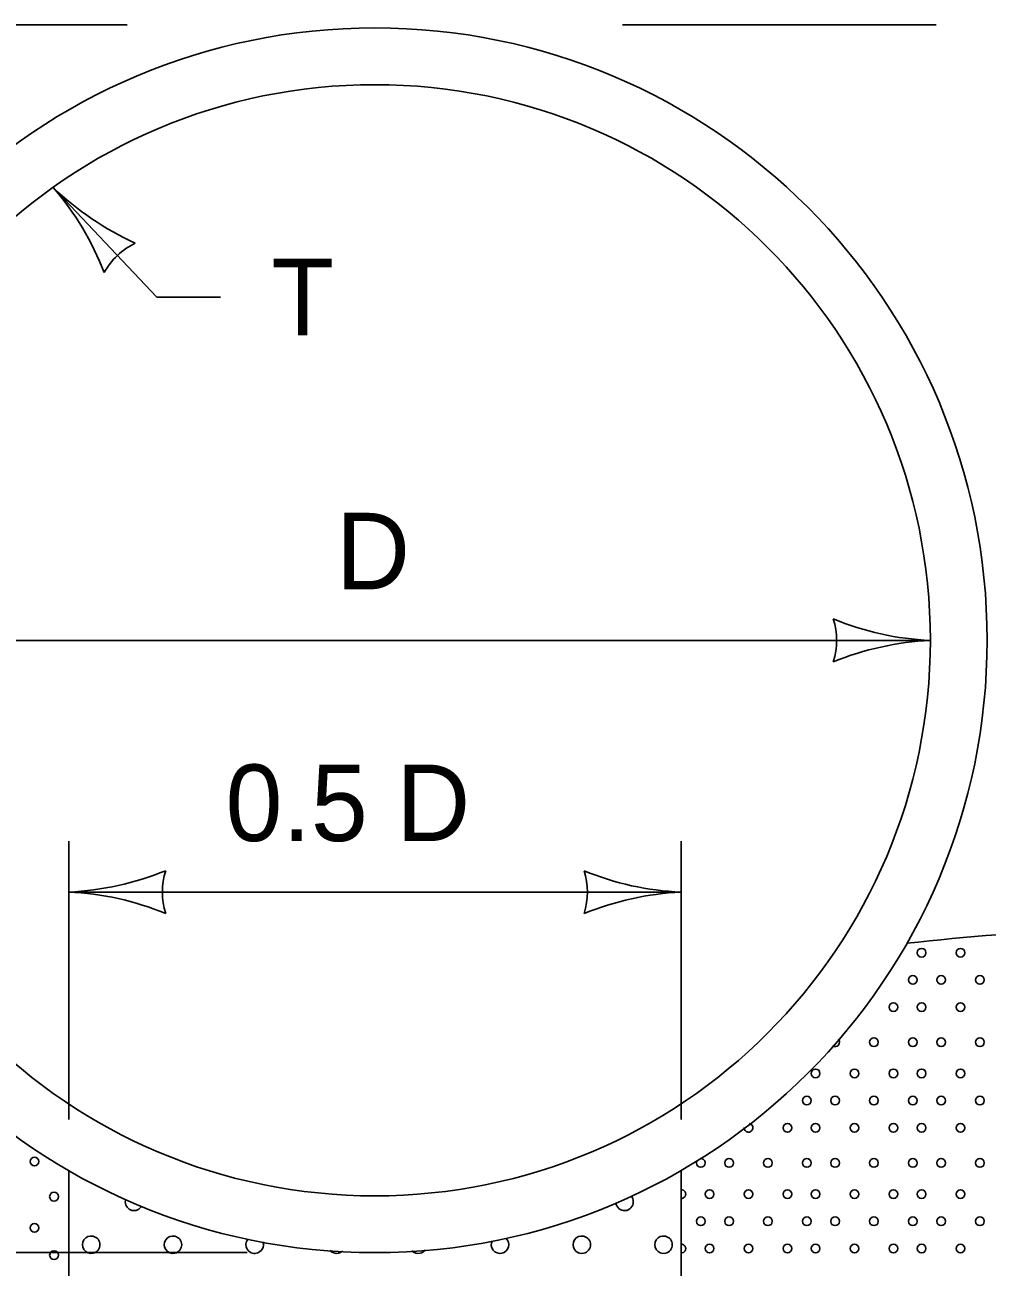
# Model space of a CAD drawing. Extents: x 49991.4 to 50021, y 49987.6 to 50011.4.
# Drawn here: x 50003.081 to 50003.835, y 49989.824 to 49990.797 of the extents above; entities that cross this region are included whole.
import ezdxf

# ---------------------------------------------------------------- set-up
doc = ezdxf.new("R2010")
doc.units = 0
for name, color, linetype in [('Level 1', 7, 'Continuous'), ('Level 2', 7, 'Continuous'), ('Level 3', 7, 'Continuous')]:
    doc.layers.add(name, color=color, linetype=linetype)

msp = doc.modelspace()

# ---------------------------------------------------------------- linework, layer by layer
at = {"layer": 'Level 1'}
for p, q in [((50001.91595, 49990.79724), (50003.16093, 49990.79724)), ((50003.54914, 49990.79724), (50003.79504, 49990.79724)), ((50003.11508, 49989.89915), (50003.11508, 49989.75269)), ((50003.59509, 49989.89921), (50003.59509, 49989.74091))]:
    msp.add_line(p, q, dxfattribs=at)
for centre, radius in [((50003.35503, 49990.31488), 0.47996), ((50003.35503, 49990.31488), 0.43545), ((50003.78366, 49990.07002), 0.00341), ((50003.81414, 49990.07002), 0.00341), ((50003.77676, 49990.04868), 0.00341), ((50003.7989, 49990.04868), 0.00341), ((50003.82938, 49990.04868), 0.00341), ((50003.82938, 49990.04868), 0.00341), ((50003.76152, 49990.02735), 0.00341), ((50003.78366, 49990.02735), 0.00341), ((50003.81414, 49990.02735), 0.00341), ((50003.70056, 49989.97542), 0.00341), ((50003.73104, 49989.97542), 0.00341), ((50003.76152, 49989.97542), 0.00341), ((50003.78366, 49989.97542), 0.00341), ((50003.81414, 49989.97542), 0.00341), ((50003.69366, 49989.95408), 0.00341), ((50003.7158, 49989.95408), 0.00341), ((50003.74628, 49989.95408), 0.00341), ((50003.74628, 49989.95408), 0.00341), ((50003.77676, 49989.95408), 0.00341), ((50003.7989, 49989.95408), 0.00341), ((50003.82938, 49989.95408), 0.00341), ((50003.82938, 49989.95408), 0.00341), ((50003.67841, 49989.93275), 0.00341), ((50003.70056, 49989.93275), 0.00341), ((50003.73104, 49989.93275), 0.00341), ((50003.76152, 49989.93275), 0.00341), ((50003.78366, 49989.93275), 0.00341), ((50003.81414, 49989.93275), 0.00341), ((50003.08831, 49989.9063), 0.00341), ((50003.61745, 49989.88082), 0.00341), ((50003.64793, 49989.88082), 0.00341), ((50003.67841, 49989.88082), 0.00341), ((50003.70056, 49989.88082), 0.00341), ((50003.73104, 49989.88082), 0.00341), ((50003.76152, 49989.88082), 0.00341), ((50003.78366, 49989.88082), 0.00341), ((50003.81414, 49989.88082), 0.00341), ((50003.61055, 49989.85948), 0.00341), ((50003.63269, 49989.85948), 0.00341), ((50003.66317, 49989.85948), 0.00341), ((50003.66317, 49989.85948), 0.00341), ((50003.69366, 49989.85948), 0.00341), ((50003.7158, 49989.85948), 0.00341), ((50003.74628, 49989.85948), 0.00341), ((50003.74628, 49989.85948), 0.00341), ((50003.77676, 49989.85948), 0.00341), ((50003.7989, 49989.85948), 0.00341), ((50003.82938, 49989.85948), 0.00341), ((50003.82938, 49989.85948), 0.00341), ((50003.08831, 49989.85437), 0.00341), ((50003.10355, 49989.83303), 0.00341), ((50003.10355, 49989.83303), 0.00341), ((50003.61745, 49989.83815), 0.00341), ((50003.64793, 49989.83815), 0.00341), ((50003.67841, 49989.83815), 0.00341), ((50003.70056, 49989.83815), 0.00341), ((50003.73104, 49989.83815), 0.00341), ((50003.76152, 49989.83815), 0.00341), ((50003.78366, 49989.83815), 0.00341), ((50003.81414, 49989.83815), 0.00341)]:
    msp.add_circle(centre, radius, dxfattribs=at)
for centre, radius, start, end in [((50003.7158, 49989.9998), 0.00341, 234.99733, 0), ((50003.7158, 49989.99992), 0.00341, 0, 44.24791), ((50003.74628, 49989.99992), 0.00341, 0, 180), ((50003.74628, 49989.9998), 0.00341, 180, 0), ((50003.74628, 49989.9998), 0.00341, 180, 0), ((50003.77676, 49989.99992), 0.00341, 0, 180), ((50003.77676, 49989.9998), 0.00341, 180, 0), ((50003.7989, 49989.99992), 0.00341, 0, 180), ((50003.7989, 49989.9998), 0.00341, 180, 0), ((50003.82938, 49989.99992), 0.00341, 0, 180), ((50003.82938, 49989.9998), 0.00341, 180, 0), ((50003.82938, 49989.9998), 0.00341, 180, 0), ((50003.64793, 49989.93275), 0.00341, 174.17681, 79.30151), ((50003.61055, 49989.90532), 0.00341, 150.81004, 180), ((50003.61055, 49989.9052), 0.00341, 180, 0), ((50003.61055, 49989.90532), 0.00341, 0, 92.56362), ((50003.63269, 49989.90532), 0.00341, 0, 180), ((50003.63269, 49989.9052), 0.00341, 180, 0), ((50003.66317, 49989.90532), 0.00341, 0, 180), ((50003.66317, 49989.9052), 0.00341, 180, 0), ((50003.66317, 49989.9052), 0.00341, 180, 0), ((50003.69366, 49989.90532), 0.00341, 0, 180), ((50003.69366, 49989.9052), 0.00341, 180, 0), ((50003.7158, 49989.90532), 0.00341, 0, 180), ((50003.7158, 49989.9052), 0.00341, 180, 0), ((50003.74628, 49989.90532), 0.00341, 0, 180), ((50003.74628, 49989.9052), 0.00341, 180, 0), ((50003.74628, 49989.9052), 0.00341, 180, 0), ((50003.77676, 49989.90532), 0.00341, 0, 180), ((50003.77676, 49989.9052), 0.00341, 180, 0), ((50003.7989, 49989.90532), 0.00341, 0, 180), ((50003.7989, 49989.9052), 0.00341, 180, 0), ((50003.82938, 49989.90532), 0.00341, 0, 180), ((50003.82938, 49989.9052), 0.00341, 180, 0), ((50003.82938, 49989.9052), 0.00341, 180, 0), ((50003.10355, 49989.87886), 0.00341, 0, 180), ((50003.59531, 49989.88082), 0.00341, 266.15567, 93.84433), ((50003.10355, 49989.87875), 0.00341, 180, 0), ((50003.10355, 49989.87875), 0.00341, 180, 0), ((50003.16623, 49989.87477), 0.00682, 162.94891, 180), ((50003.16623, 49989.87468), 0.00682, 180, 331.78001), ((50003.55083, 49989.87468), 0.00682, 185.22689, 0), ((50003.55083, 49989.87477), 0.00682, 0, 41.43459), ((50003.13261, 49989.84115), 0.00682, 77.07903, 282.92097), ((50003.1327, 49989.84115), 0.00682, 282.92097, 77.07903), ((50003.19671, 49989.84115), 0.00682, 77.07903, 282.92097), ((50003.1968, 49989.84115), 0.00682, 282.92097, 77.07903), ((50003.26081, 49989.84115), 0.00682, 139.87286, 282.92097), ((50003.2609, 49989.84115), 0.00682, 282.92097, 18.76841), ((50003.45311, 49989.84115), 0.00682, 153.05115, 282.92097), ((50003.4532, 49989.84115), 0.00682, 282.92097, 46.88414), ((50003.51721, 49989.84115), 0.00682, 77.07903, 282.92097), ((50003.5173, 49989.84115), 0.00682, 282.92097, 77.07903), ((50003.58131, 49989.84115), 0.00682, 77.07903, 282.92097), ((50003.5814, 49989.84115), 0.00682, 282.92097, 77.07903), ((50003.32491, 49989.84115), 0.00682, 221.16252, 282.92097), ((50003.325, 49989.84115), 0.00682, 282.92097, 313.64891), ((50003.38901, 49989.84115), 0.00682, 223.67216, 282.92097), ((50003.3891, 49989.84115), 0.00682, 282.92097, 323.09273), ((50003.59531, 49989.83815), 0.00341, 266.15567, 93.84433)]:
    msp.add_arc(centre, radius, start, end, dxfattribs=at)
msp.add_spline([(50003.77217, 49990.07737), (50003.91341, 49990.08547), (50004.05703, 49990.0772), (50004.17388, 49990.08608), (50004.17865, 49990.08552)], degree=3, dxfattribs=at)
at = {"layer": 'Level 3'}
for p, q in [((50003.18422, 49990.58385), (50003.10277, 49990.66982)), ((50003.18422, 49990.58385), (50003.23396, 49990.58385)), ((50002.91958, 49990.31481), (50003.79049, 49990.31481)), ((50003.11508, 49989.93925), (50003.11508, 49990.15745)), ((50003.59509, 49989.93925), (50003.59509, 49990.15745)), ((50003.11508, 49990.1175), (50003.59509, 49990.1175)), ((50002.1895, 49989.83493), (50003.25502, 49989.83493))]:
    msp.add_line(p, q, dxfattribs=at)
for centre, radius, start, end in [((50002.93521, 49990.52368), 0.22232, 20.90984, 41.09335), ((50003.2638, 49990.83821), 0.233, 226.28114, 245.53099), ((50003.19095, 49990.57674), 0.05478, 115.59265, 151.31501), ((50003.79965, 49990.53694), 0.22232, 247.45601, 267.63952), ((50003.66227, 49990.31481), 0.05478, 342.13882, 17.86118), ((50003.80198, 49990.08209), 0.233, 92.82731, 112.07716), ((50003.10359, 49990.35021), 0.233, 272.82731, 292.07716), ((50003.2433, 49990.1175), 0.05478, 162.13882, 197.86118), ((50003.60424, 49990.33964), 0.22232, 247.45601, 267.63952), ((50003.46687, 49990.1175), 0.05478, 342.13882, 17.86118), ((50003.10592, 49989.89536), 0.22232, 67.45601, 87.63952), ((50003.60658, 49989.88478), 0.233, 92.82731, 112.07716)]:
    msp.add_arc(centre, radius, start, end, dxfattribs=at)

# ---------------------------------------------------------------- texts
at = {"layer": 'Level 2'}
for s, p in [('T', (50003.27396, 49990.55385)), ('D', (50003.32467, 49990.35481)), ('0.5 D', (50003.238, 49990.1575))]:
    msp.add_text(s, height=0.06, dxfattribs=at).set_placement(p)

doc.saveas('drawing.dxf')
